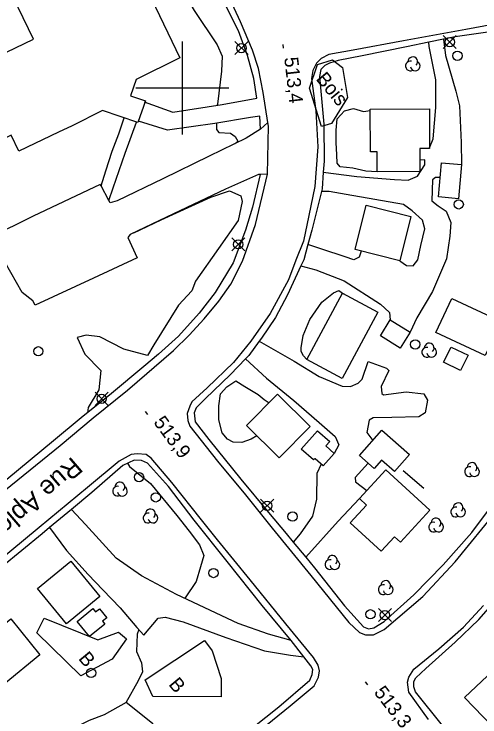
# Model space of a CAD drawing. Extents: x 347312 to 350503, y 6073086 to 6076432.
# Drawn here: x 348863.8 to 348964.1, y 6074464.5 to 6074615.9 of the extents above; entities that cross this region are included whole.
import ezdxf

# ---------------------------------------------------------------- set-up
doc = ezdxf.new("R2010")
doc.units = 0
for name, color, linetype in [('Level 19', 7, 'Continuous'), ('Level 2', 7, 'Continuous'), ('Level 21', 7, 'Continuous'), ('Level 22', 7, 'Continuous'), ('Level 3', 7, 'Continuous'), ('Level 31', 7, 'Continuous'), ('Level 36', 7, 'Continuous'), ('Level 37', 7, 'Continuous'), ('Level 44', 7, 'Continuous'), ('Level 61', 7, 'Continuous')]:
    doc.layers.add(name, color=color, linetype=linetype)

msp = doc.modelspace()

# ---------------------------------------------------------------- linework, layer by layer
at = {"layer": 'Level 19'}
for points in [[(348953.24, 6074587.12), (348953.98, 6074589.02), (348954.59, 6074595.82), (348954.6, 6074601.74), (348953.16, 6074608.93), (348953.04, 6074609.85)], [(348956.23, 6074610.49), (348956.66, 6074606.98), (348958.88, 6074599.31), (348959.64, 6074596.17), (348960.04, 6074588.25), (348960.12, 6074583.51)], [(348918.43, 6074592.55), (348916.87, 6074591.16), (348913.79, 6074589.18), (348905.77, 6074585.31), (348895.82, 6074580.42), (348886, 6074575.72), (348884.53, 6074575.24), (348884.25, 6074575.76), (348882.54, 6074578.9), (348882.36, 6074579.23), (348867.9, 6074572.37), (348863.63, 6074570.27), (348861.9, 6074569.42), (348860.77, 6074568.86)], [(348930.36, 6074581.87), (348937.55, 6074580.96), (348945.65, 6074580.29), (348948.62, 6074580.13), (348950.65, 6074581.02), (348952.21, 6074583.47), (348952.18, 6074584.5), (348951.15, 6074584.46)], [(348918.32, 6074581.42), (348916.79, 6074581.35), (348916.43, 6074581.33), (348909.29, 6074578.2), (348898.12, 6074572.88), (348888.78, 6074568.43), (348888.27, 6074567.77), (348890.29, 6074563.42), (348880.91, 6074559.01), (348868.35, 6074553.21), (348867.86, 6074554.16), (348865.56, 6074555.96), (348861.88, 6074562.38), (348861.01, 6074566.78), (348860.77, 6074568.86)], [(348955.52, 6074580.71), (348954.53, 6074580.71), (348953.88, 6074580.23), (348953.72, 6074575.72), (348955.09, 6074574.6), (348956.8, 6074573.47), (348957.82, 6074571), (348957.57, 6074568.07), (348956.83, 6074563.21), (348953.86, 6074556.17), (348950.51, 6074550.47), (348949.03, 6074547.4)], [(348946.79, 6074562.77), (348948.24, 6074561.73), (348949.71, 6074561.67), (348950.72, 6074562.98), (348951.31, 6074566.05), (348952.19, 6074569.66), (348951.69, 6074571.51), (348949.47, 6074573.57), (348949.47, 6074573.57), (348947.64, 6074574.9), (348935.3, 6074577.07), (348931.64, 6074577.7), (348929.99, 6074577.7)], [(348938.51, 6074564.85), (348938.07, 6074563.57), (348936.92, 6074562.98), (348935.05, 6074563.61), (348930.07, 6074565.31), (348927.05, 6074566.26)], [(348925.54, 6074561.68), (348928.77, 6074560.85), (348934.84, 6074558.47), (348942.67, 6074553.42), (348944.63, 6074551.67), (348944.75, 6074550.06)], [(348916.58, 6074545.46), (348924.07, 6074541.18), (348929.49, 6074537.88), (348934.44, 6074535.78), (348936.19, 6074535.74), (348937.84, 6074536.45), (348938.73, 6074537.27), (348940.01, 6074541.07), (348943.93, 6074539.68), (348944.45, 6074539.14), (348942.84, 6074535.74), (348942.98, 6074534.2), (348943.29, 6074533.93), (348948.2, 6074534.59), (348951.99, 6074534.15), (348952.81, 6074532.8), (348952.27, 6074530.01), (348950.89, 6074529.15), (348945.13, 6074529.06), (348941.12, 6074528.94), (348940.22, 6074528.48), (348939.74, 6074525.81), (348941, 6074524.09)], [(348913.62, 6074541.66), (348918.11, 6074537.49), (348924, 6074532.7), (348929.49, 6074527.95), (348932.94, 6074524.94), (348933.72, 6074523.17), (348932.73, 6074521.26)], [(348929.92, 6074519), (348929, 6074516.94), (348928.92, 6074511.43), (348928.02, 6074507.8), (348925.39, 6074504.01), (348923.88, 6074502.21)], [(348939.99, 6074519.2), (348937.18, 6074516.08), (348937.3, 6074515.2), (348939.74, 6074513.29)], [(348926.59, 6074498.93), (348933.53, 6074506.74), (348938.15, 6074511.56)], [(348923.43, 6074481.03), (348918.58, 6074482.38), (348912.05, 6074484.67), (348898.74, 6074490.92), (348891.23, 6074494.94), (348885.82, 6074498.77), (348879.2, 6074505.97), (348876.15, 6074509.21)], [(348871.44, 6074505.31), (348875.08, 6074500.36), (348879.8, 6074495.19), (348882.94, 6074491.94), (348886.62, 6074488.02), (348890.25, 6074483.82), (348891.77, 6074482.16), (348894.83, 6074485.79), (348896.36, 6074486.02), (348900.18, 6074485.01), (348909.39, 6074481.65), (348917.69, 6074478.75), (348923.32, 6074477.82), (348926.18, 6074477.5)], [(348903.21, 6074452.61), (348898.9, 6074457.29), (348893.63, 6074463.12), (348887.95, 6074467.63), (348883.19, 6074464.98), (348879.98, 6074463.79), (348874.86, 6074461.22), (348872.05, 6074459.46), (348865.53, 6074455.94), (348864.04, 6074456.12), (348862.55, 6074456.83), (348861.59, 6074457.99), (348860.3, 6074462.63), (348860.12, 6074469.35), (348860.79, 6074472.71)]]:
    msp.add_lwpolyline(points, dxfattribs=at)
at = {"layer": 'Level 2'}
for points in [[(348900.73, 6074619.88), (348902.59, 6074616.7), (348907.52, 6074609.27), (348908.57, 6074606.82), (348908.49, 6074603.65), (348907.56, 6074596.51), (348907.55, 6074596.27)], [(348941.97, 6074581.97), (348939.49, 6074582.08), (348936.73, 6074582.71), (348933.99, 6074583.04), (348933.32, 6074583.77), (348933.24, 6074585.59), (348933.15, 6074588.24), (348933.1, 6074590.92), (348933.32, 6074593.37), (348934.94, 6074595.04), (348936.87, 6074595.6), (348939.01, 6074594.91), (348940.46, 6074595.12)], [(348907.41, 6074592.4), (348907.36, 6074591.05), (348907.87, 6074590.42), (348910.39, 6074590.27), (348911.43, 6074589.55), (348911.99, 6074588.51), (348911.35, 6074588)], [(348889.56, 6074568.8), (348889.6, 6074568.77), (348895.44, 6074571.57), (348906.13, 6074576.48), (348910.17, 6074577.83), (348912.65, 6074576.74), (348912.9, 6074575.52), (348912.01, 6074571.44), (348907.79, 6074565.4), (348902.88, 6074558.39), (348902.07, 6074556.28), (348899.23, 6074553.2), (348893.93, 6074544.67), (348892.5, 6074542.41), (348887.44, 6074543.74), (348882.25, 6074546.4), (348879.34, 6074546.76), (348877.42, 6074546.27), (348879.05, 6074542.66), (348882.46, 6074539.17), (348882.08, 6074535), (348879.74, 6074531.22), (348879.64, 6074530.07)], [(348926.8, 6074541.52), (348926.1, 6074542.29), (348925.61, 6074543.24), (348925.6, 6074544.07), (348926, 6074546.67), (348927.49, 6074550.12), (348930.03, 6074553.84), (348932.54, 6074555.87), (348933.69, 6074556.39), (348934.67, 6074555.67)], [(348916.07, 6074525.1), (348914.86, 6074524.38), (348912.84, 6074523.66), (348910.97, 6074523.75), (348909.72, 6074524.36), (348908.58, 6074525.74), (348907.85, 6074528.53), (348907.88, 6074531.58), (348908.27, 6074534.1), (348909.59, 6074535.66), (348911.54, 6074536.92), (348913.47, 6074535.68), (348916.34, 6074534.01), (348917.63, 6074532.9), (348918.68, 6074532.22)], [(348888.23, 6074519.17), (348888.69, 6074518.51), (348893.15, 6074514.82), (348898.87, 6074507.96), (348901.47, 6074504.52), (348903.74, 6074501.6), (348904.68, 6074499.29), (348903.93, 6074496.87), (348902.99, 6074493.74), (348900.64, 6074490.19), (348900.5, 6074490.09)], [(348890.67, 6074483.35), (348890.31, 6074482.4), (348890.14, 6074478.64), (348891.23, 6074476.22), (348891.43, 6074474.25), (348890.54, 6074472.29), (348887.88, 6074467.59)]]:
    msp.add_lwpolyline(points, dxfattribs=at)
at = {"layer": 'Level 21'}
for points in [[(348845.52, 6074499.78), (348852.09, 6074505.23), (348862, 6074513.43), (348873.72, 6074522.98), (348880.83, 6074528.95), (348888.26, 6074534.9), (348898.13, 6074543.43), (348901.49, 6074546.79), (348904.7, 6074550.25), (348907.86, 6074554.12), (348910.43, 6074557.71), (348912.96, 6074562.72), (348915.75, 6074570.58), (348918.32, 6074581.42), (348918.55, 6074591.77), (348918.43, 6074592.55), (348917.45, 6074599.02), (348916.4, 6074604.19), (348915.12, 6074608.11), (348912.56, 6074614.21), (348908.42, 6074623.14)], [(348973.44, 6074614.86), (348961.01, 6074612.57), (348947.58, 6074610.13), (348936.81, 6074608.11), (348931.56, 6074607.17), (348929.93, 6074606.32), (348928.86, 6074605.35), (348928.07, 6074603.77), (348927.83, 6074602.06), (348928.72, 6074595.09), (348929.2, 6074587.33), (348928.52, 6074578.81), (348927.26, 6074572.53), (348926.07, 6074566.99), (348924.43, 6074562.89), (348922.87, 6074558.71), (348918.95, 6074551.4), (348914.79, 6074545.48), (348911.03, 6074540.88), (348905.35, 6074535.43), (348902.1, 6074532.39), (348901.65, 6074531.48), (348901.1, 6074529.89), (348901.21, 6074528.39), (348901.64, 6074527.15)], [(348901.64, 6074527.15), (348907.61, 6074519.64), (348913.61, 6074512.37), (348919.38, 6074505.21), (348927.64, 6074495.02), (348935.86, 6074484.87), (348938.15, 6074482.73), (348939.46, 6074482.24), (348941.17, 6074482.25), (348943.44, 6074483.4), (348951.78, 6074490.5), (348958.73, 6074497.93), (348967.96, 6074509.31)], [(348914.51, 6074459.85), (348923.26, 6074466.91), (348928.38, 6074471.22), (348929.36, 6074473.1), (348929.57, 6074474.48), (348929.23, 6074475.71), (348928.24, 6074477.36), (348922.32, 6074484.62), (348914.6, 6074494.05), (348907.63, 6074502.68), (348904.18, 6074506.96), (348897.76, 6074515), (348893.33, 6074520.27), (348892.22, 6074521.07), (348890.31, 6074521.21), (348889, 6074521.08), (348886.46, 6074519.63), (348879.62, 6074513.95), (348869.26, 6074505.31), (348859.88, 6074497.64)], [(348952.97, 6074464.02), (348948.73, 6074469.88), (348948.47, 6074472.01), (348948.74, 6074473.13), (348949.87, 6074474.84), (348955.24, 6074479.21), (348960.51, 6074483.87), (348964.81, 6074488.54)]]:
    msp.add_lwpolyline(points, dxfattribs=at)
at = {"layer": 'Level 22'}
for points in [[(348891.79, 6074597), (348897.96, 6074594.77), (348908.57, 6074596.43), (348916.04, 6074597.8), (348915.4, 6074602.02), (348914.05, 6074607.02), (348912.11, 6074612.28), (348908.62, 6074619.33), (348906.78, 6074622.93), (348900.48, 6074619.76), (348897.55, 6074618.42), (348896.01, 6074617.74)], [(348968.24, 6074612.39), (348958.76, 6074611), (348956.23, 6074610.49), (348953.04, 6074609.85), (348948.23, 6074608.88), (348938.75, 6074606.95), (348933.57, 6074605.93), (348931.68, 6074605.31), (348930.69, 6074604.86), (348929.84, 6074603.99), (348929.54, 6074602.45), (348930.49, 6074592.21), (348930.51, 6074584.21), (348930.36, 6074581.87), (348930.14, 6074578.3), (348929.99, 6074577.7), (348927.91, 6074569.39), (348927.05, 6074566.26), (348926.15, 6074563), (348925.54, 6074561.68), (348922.66, 6074555.45), (348920.05, 6074550.54), (348917.09, 6074546.15), (348916.58, 6074545.46), (348914.34, 6074542.41), (348913.62, 6074541.66), (348910.39, 6074538.32), (348904.93, 6074533.06), (348903.04, 6074531.09), (348902.58, 6074530.02), (348902.81, 6074528.1), (348905.74, 6074524.29), (348912.64, 6074515.74), (348918.56, 6074508.57), (348922.36, 6074504.06), (348923.88, 6074502.21), (348926.59, 6074498.93), (348928.47, 6074496.66), (348934.91, 6074488.49), (348938.98, 6074483.92), (348940.08, 6074483.49), (348941.21, 6074483.76), (348943.45, 6074485.12), (348949.8, 6074490.83), (348956.13, 6074497.29), (348962.31, 6074504.3), (348969.59, 6074513.97)], [(348882.54, 6074578.9), (348883.54, 6074582.17), (348884.94, 6074586.37), (348886.35, 6074590.15), (348887.48, 6074593.57)], [(348884.25, 6074575.76), (348885.15, 6074578.48), (348887.73, 6074585.95), (348890.14, 6074592.65)], [(348916.87, 6074591.16), (348916.67, 6074593.94), (348914.72, 6074593.67), (348907, 6074592.33), (348896.87, 6074590.92), (348890.58, 6074592.83)], [(348916.79, 6074581.35), (348915.12, 6074574.33), (348913.61, 6074569.35), (348910.94, 6074562.34), (348907.1, 6074555.94), (348903.64, 6074551.52), (348899.23, 6074546.52), (348894.88, 6074542.64), (348891.75, 6074540), (348884.78, 6074534.21), (348878.27, 6074528.96), (348872.31, 6074524.03), (348862.26, 6074515.65), (348853.27, 6074508.32), (348844.96, 6074501.63), (348839.87, 6074497.19), (348836.14, 6074494.28), (348833.59, 6074492.66), (348831.71, 6074491.77), (348830.28, 6074491.32), (348826.13, 6074490.1), (348823.52, 6074490.09), (348818.94, 6074490.47), (348818.42, 6074488.95)], [(348912.74, 6074460.34), (348920.82, 6074466.76), (348927.46, 6074472.49), (348927.97, 6074473.67), (348928.11, 6074474.77), (348927.69, 6074475.55), (348926.18, 6074477.5), (348923.43, 6074481.03), (348917.24, 6074488.57), (348909.68, 6074497.99), (348902.57, 6074506.89), (348897.06, 6074514.19), (348892.53, 6074519.22), (348891.27, 6074519.75), (348889.69, 6074519.85), (348887.26, 6074518.71), (348880.58, 6074512.86), (348876.15, 6074509.21), (348871.44, 6074505.31), (348869.86, 6074504), (348861.14, 6074496.82)], [(348956.02, 6074462.74), (348950.19, 6074469.98), (348949.8, 6074471), (348949.82, 6074472.15), (348950.26, 6074472.97), (348952.4, 6074475), (348958.74, 6074480.64), (348963.79, 6074485.56), (348967.5, 6074489.67)]]:
    msp.add_lwpolyline(points, dxfattribs=at)
at = {"layer": 'Level 3'}
for p, q in [((348921.66, 6074609.37), (348921.74, 6074608.57)), ((348892.03, 6074530.31), (348892.5, 6074529.67)), ((348939.4, 6074472.11), (348939.89, 6074471.48))]:
    msp.add_line(p, q, dxfattribs=at)
at = {"layer": 'Level 31'}
for points in [[(348865.52, 6074677.41), (348899.47, 6074606.52), (348890.12, 6074601.84), (348888.91, 6074598.31), (348892.09, 6074597.22), (348890.48, 6074592.53), (348882.86, 6074595.17)], [(348882.86, 6074595.17), (348876.31, 6074591.86), (348873.39, 6074590.46), (348864.84, 6074586.36), (348863.19, 6074589.8), (348853.62, 6074585.21), (348846.46, 6074600.15), (348868.01, 6074610.47), (348861.41, 6074624.25)], [(348940.46, 6074595.45), (348953.19, 6074595.52), (348953.24, 6074586.94), (348951.13, 6074586.93), (348951.16, 6074582.03), (348941.97, 6074581.97), (348941.94, 6074586.23), (348940.52, 6074586.22), (348940.46, 6074595.45)], [(348955.14, 6074576.54), (348955.8, 6074583.9), (348960.12, 6074583.51), (348959.45, 6074576.15), (348955.14, 6074576.54)], [(348937.2, 6074565.18), (348939.61, 6074574.75), (348949.19, 6074572.33), (348946.79, 6074562.77), (348937.2, 6074565.18)], [(348942.08, 6074551.69), (348934.43, 6074537.43), (348926.8, 6074541.52), (348934.46, 6074555.78), (348942.08, 6074551.69)], [(348954.57, 6074547.33), (348958, 6074554.67), (348968.6, 6074549.71), (348965.17, 6074542.38), (348954.57, 6074547.33)], [(348944.75, 6074550.06), (348949.03, 6074547.4), (348946.91, 6074543.99), (348942.63, 6074546.65), (348944.75, 6074550.06)], [(348957.86, 6074544.2), (348961.49, 6074542.43), (348959.88, 6074539.14), (348956.25, 6074540.92), (348957.86, 6074544.2)], [(348913.83, 6074527.32), (348920.5, 6074534.06), (348927.51, 6074527.11), (348920.84, 6074520.37), (348913.83, 6074527.32)], [(348925.61, 6074522.24), (348929.14, 6074526.19), (348931.74, 6074523.87), (348930.88, 6074522.91), (348932.73, 6074521.26), (348930.36, 6074518.6), (348928.63, 6074520.15), (348928.55, 6074520.22), (348928.25, 6074519.88), (348925.61, 6074522.24)], [(348948.89, 6074521.08), (348945.65, 6074517.4), (348942.86, 6074519.85), (348941.29, 6074518.06), (348938.13, 6074520.83), (348942.95, 6074526.31), (348948.89, 6074521.08)], [(348943.81, 6074517.73), (348953.28, 6074509.05), (348946.99, 6074502.19), (348945.71, 6074503.36), (348942.84, 6074500.23), (348936.17, 6074506.35), (348939.67, 6074510.17), (348938.15, 6074511.56), (348943.81, 6074517.73)], [(348868.86, 6074492.22), (348876.01, 6074498.08), (348882.26, 6074490.46), (348875.11, 6074484.59), (348868.86, 6074492.22)], [(348883.36, 6074484.55), (348880.07, 6074481.86), (348877.4, 6074485.12), (348880.77, 6074487.87), (348881.36, 6074487.15), (348882.2, 6074487.84), (348883.8, 6074485.9), (348882.88, 6074485.14), (348883.36, 6074484.55)], [(348855.38, 6074479.37), (348863.1, 6074485.64), (348869.39, 6074477.9), (348861.67, 6074471.63), (348855.38, 6074479.37)], [(348972.85, 6074468.29), (348966.73, 6074462.47), (348960.75, 6074468.75), (348966.87, 6074474.58), (348972.85, 6074468.29)]]:
    msp.add_lwpolyline(points, dxfattribs=at)
at = {"layer": 'Level 36'}
for p, q in [((348956.15, 6074608.46), (348958.97, 6074611.28)), ((348956.15, 6074611.28), (348958.97, 6074608.46)), ((348911.34, 6074607.17), (348914.16, 6074609.99)), ((348911.34, 6074609.99), (348914.16, 6074607.17)), ((348910.65, 6074564.91), (348913.47, 6074567.73)), ((348910.65, 6074567.73), (348913.47, 6074564.91)), ((348881.26, 6074531.65), (348884.08, 6074534.47)), ((348881.26, 6074534.47), (348884.08, 6074531.65)), ((348916.87, 6074508.61), (348919.69, 6074511.43)), ((348916.87, 6074511.43), (348919.69, 6074508.61)), ((348942.21, 6074485.07), (348945.03, 6074487.89)), ((348942.21, 6074487.89), (348945.03, 6074485.07))]:
    msp.add_line(p, q, dxfattribs=at)
for centre in [(348957.56, 6074609.87), (348912.75, 6074608.58), (348959.21, 6074606.93), (348959.49, 6074574.93), (348912.06, 6074566.32), (348950.14, 6074544.77), (348869.05, 6074543.29), (348882.67, 6074533.06), (348890.71, 6074516.2), (348894.32, 6074511.83), (348918.28, 6074510.02), (348923.75, 6074507.7), (348906.73, 6074495.54), (348940.5, 6074486.65), (348943.62, 6074486.48), (348880.39, 6074474.02)]:
    msp.add_circle(centre, 1, dxfattribs=at)
at = {"layer": 'Level 37'}
msp.add_lwpolyline([(348951.97, 6074513.74), (348947.51, 6074517.53)], dxfattribs=at)
at = {"layer": 'Level 44'}
for points in [[(348934.5, 6074604.44), (348935.58, 6074597.95), (348932.15, 6074592.35), (348929.97, 6074591.72), (348927.37, 6074599.95), (348929.14, 6074605.06), (348932.33, 6074606.09), (348934.5, 6074604.44)], [(348884.95, 6074476.97), (348878.19, 6074473.39), (348868.75, 6074482.65), (348870.33, 6074485.8), (348881.82, 6074481.12), (348886.29, 6074482.77), (348888.04, 6074481.38), (348884.95, 6074476.97)], [(348908.37, 6074468.9), (348893.69, 6074468.93), (348892.06, 6074472.54), (348904.81, 6074481), (348906.48, 6074478.78), (348908.4, 6074472.85), (348908.37, 6074468.9)]]:
    msp.add_lwpolyline(points, dxfattribs=at)
for centre, start, end in [((348949.61, 6074605.64), 314.0633, 179.7519), ((348949.09, 6074604.74), 76.8848, 299.5691), ((348950.14, 6074604.74), 192.2171, 59.6742), ((348953.14, 6074543.99), 314.0633, 179.7519), ((348952.62, 6074543.09), 76.8848, 299.5691), ((348953.67, 6074543.09), 192.2171, 59.6742), ((348962.35, 6074518.27), 314.0633, 179.7519), ((348961.83, 6074517.37), 76.8848, 299.5691), ((348962.88, 6074517.37), 192.2171, 59.6742), ((348886.08, 6074513.17), 76.8848, 299.5691), ((348886.6, 6074514.07), 314.0633, 179.7519), ((348887.13, 6074513.17), 192.2171, 59.6742), ((348958.85, 6074508.69), 76.8848, 299.5691), ((348959.37, 6074509.59), 314.0633, 179.7519), ((348959.9, 6074508.69), 192.2171, 59.6742), ((348892.65, 6074507.38), 76.8848, 299.5691), ((348893.17, 6074508.28), 314.0633, 179.7519), ((348893.7, 6074507.38), 192.2171, 59.6742), ((348954.09, 6074505.43), 76.8848, 299.5691), ((348954.61, 6074506.33), 314.0633, 179.7519), ((348955.14, 6074505.43), 192.2171, 59.6742), ((348932.3, 6074498.27), 314.0633, 179.7519), ((348931.78, 6074497.37), 76.8848, 299.5691), ((348932.83, 6074497.37), 192.2171, 59.6742), ((348943.26, 6074491.96), 76.8848, 299.5691), ((348943.78, 6074492.86), 314.0633, 179.7519), ((348944.31, 6074491.96), 192.2171, 59.6742)]:
    msp.add_arc(centre, 1.05, start, end, dxfattribs=at)
at = {"layer": 'Level 61'}
for p, q in [((348900, 6074610), (348900, 6074590)), ((348890, 6074600), (348910, 6074600))]:
    msp.add_line(p, q, dxfattribs=at)

# ---------------------------------------------------------------- texts
at = {"layer": 'Level 21'}
msp.add_text('Rue Aplow', height=4, rotation=220.6505, dxfattribs=at).set_placement((348876.34, 6074520.74))
at = {"layer": 'Level 3'}
for s, rotation, p in [('513,4', 276.3993, (348921.94, 6074606.5)), ('513,9', 306.4917, (348893.71, 6074527.98)), ('513,3', 307.5605, (348941.13, 6074469.8))]:
    msp.add_text(s, height=3, rotation=rotation, dxfattribs=at).set_placement(p)
at = {"layer": 'Level 44'}
for s, p in [('Bois', (348928.63, 6074601.88)), ('B', (348877.54, 6074477.07)), ('B', (348896.94, 6074471.51))]:
    msp.add_text(s, height=3, rotation=309.568, dxfattribs=at).set_placement(p)

doc.saveas('drawing.dxf')
